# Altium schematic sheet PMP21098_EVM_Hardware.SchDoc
size 431 x 279 mm; Date: Not shown in title block; ApprovedBy: Not shown in title block; CheckedBy: Not shown in title block; Author: Not shown in title block; CompanyName: Not shown in title block; Engineer: Not shown in title block; Organization: Not shown in title block; Address1: Not shown in title block; Address2: Not shown in title block; Address3: Not shown in title block; Address4: Not shown in title block; DocumentNumber: 3; Revision: Use project parameter SCH_Rev; SheetNumber: 3; SheetTotal: 3; PageSetup: Record=PageOptions¦CenterHorizontal=True¦CenterVertical=True¦PrintScale=1.00¦XCorrection=1.00¦YCorrection=1.00¦PrintKind=0¦BorderSize=5000000¦LeftOffset=0¦BottomOffset=0¦Orientation=2¦PaperLength=1000¦PaperWidth=1000¦Scale=100¦PaperSource=15¦PrintQuality=600¦MediaType=1¦DitherType=10¦PaperKind=Letter¦PrintScaleMode=1
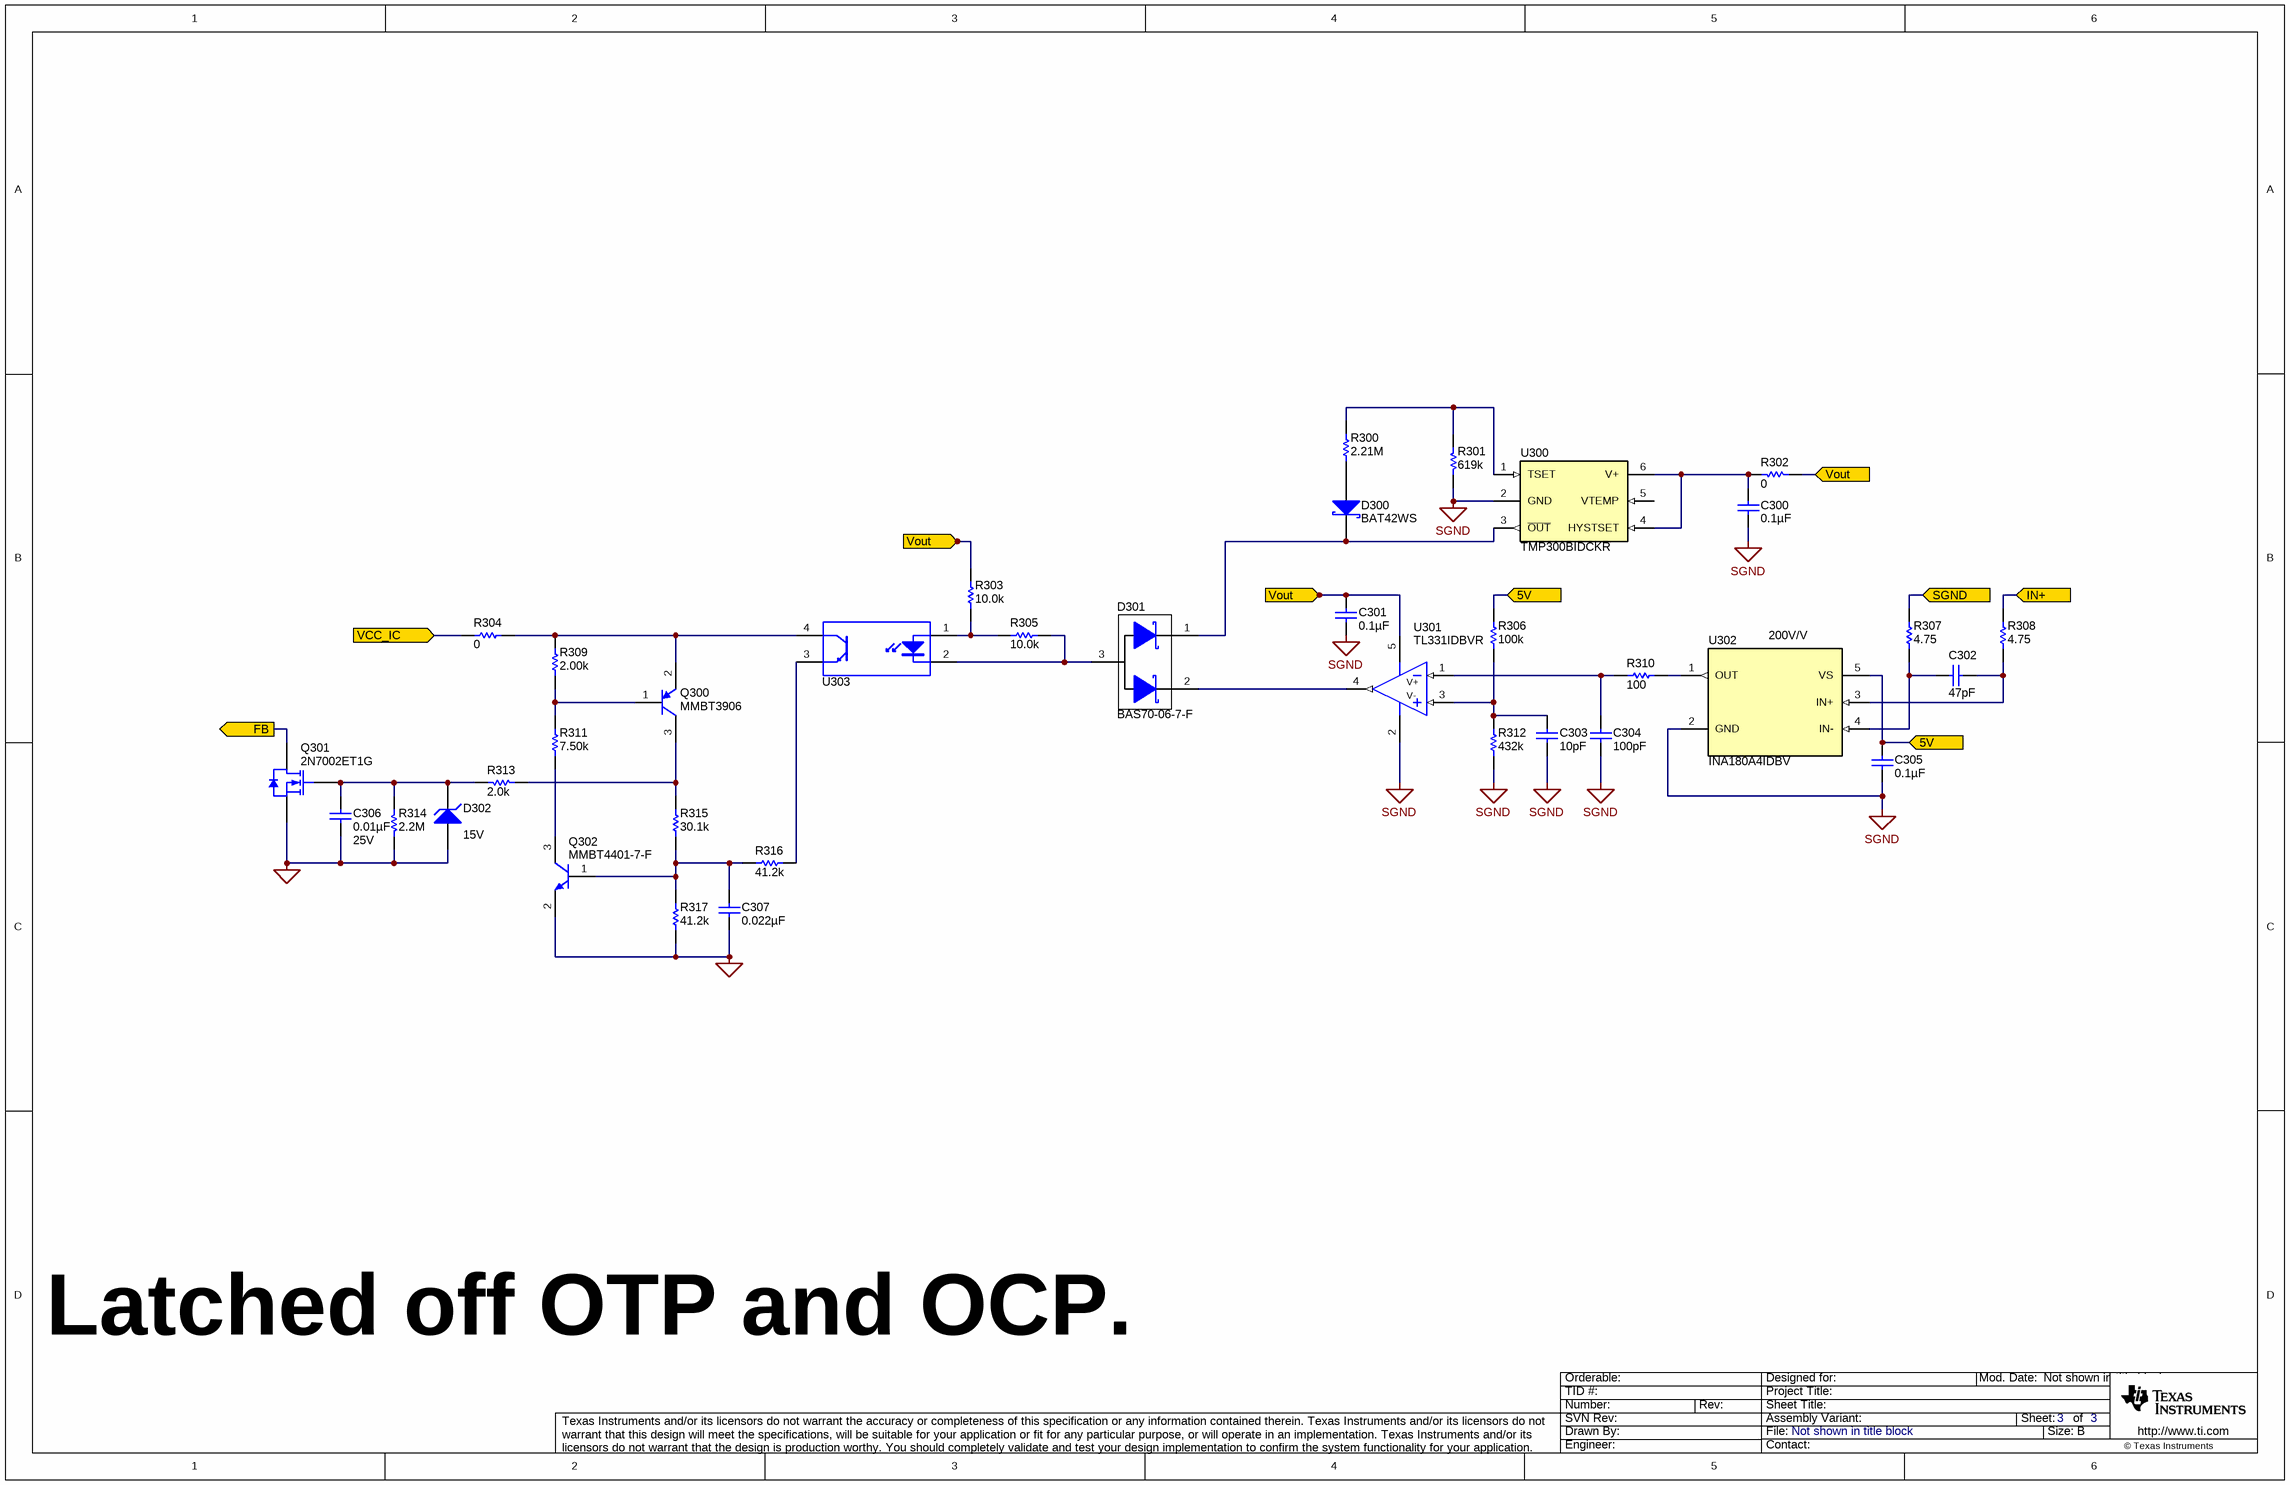
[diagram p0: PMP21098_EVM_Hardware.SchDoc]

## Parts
C300  ValueDisplayed: 0.1µF  [0402]  (hidden comment: GRM155R61C104KA88D)
C301  ValueDisplayed: 0.1µF  [0402]  (hidden comment: GRM155R61C104KA88D)
C302  ValueDisplayed: 47pF  [1206]  (hidden comment: 12067A470JAT2A)
C303  ValueDisplayed: 10pF  [0402]  (hidden comment: GRM1555C1H100RA01D)
C304  ValueDisplayed: 100pF  [0402]  (hidden comment: GRM1555C1H101JA01D)
C305  ValueDisplayed: 0.1µF  [0402]  (hidden comment: GRM155R61E104KA87D)
C306  ValueDisplayed: 0.01µF  Value2: 25V  [0603]  (hidden comment: C0603C103J3GECAUTO)
C307  ValueDisplayed: 0.022µF  [0603]  (hidden comment: C0603C223K5RACTU)
D300  BAT42WS  [sod-323]
D301  BAS70-06-7-F  [SOT-23]
D302  value 15V  [SOD-523]  (hidden comment: MM5Z15VT1G)
Q300  MMBT3906  [SOT-23]
Q301  2N7002ET1G  [SOT-23]
Q302  MMBT4401-7-F  [SOT-23]
R300  ValueDisplayed: 2.21M  [0603]  (hidden comment: CRCW06032M21FKEA)
R301  value 619k  [0402]  (hidden comment: CRCW0402619KFKED)
R302  value 0  [0402]  (hidden comment: ERJ-2GE0R00X)
R303  ValueDisplayed: 10.0k  [0603]  (hidden comment: CRCW060310K0FKEA)
R304  ValueDisplayed: 0  [0603]  (hidden comment: CRCW06030000Z0EA)
R305  ValueDisplayed: 10.0k  [0603]  (hidden comment: CRCW060310K0FKEA)
R306  ValueDisplayed: 100k  [0402]  (hidden comment: CRCW0402100KFKED)
R307  ValueDisplayed: 4.75  [0402]  (hidden comment: CRCW04024R75FKED)
R308  ValueDisplayed: 4.75  [0402]  (hidden comment: CRCW04024R75FKED)
R309  ValueDisplayed: 2.00k  [CPF0603]  (hidden comment: CPF0603B2K0E)
R310  ValueDisplayed: 100  [0402]  (hidden comment: ATC504L1000FTNCFT)
R311  ValueDisplayed: 7.50k  [0603]  (hidden comment: RC0603FR-077K5L)
R312  ValueDisplayed: 432k  [0603]  (hidden comment: CRCW0603432KFKEA)
R313  ValueDisplayed: 2.0k  [0603]  (hidden comment: RC0603JR-072KL)
R314  ValueDisplayed: 2.2M  [0603]  (hidden comment: CRCW06032M20JNEA)
R315  ValueDisplayed: 30.1k  [0603]  (hidden comment: CRCW060330K1FKEA)
R316  ValueDisplayed: 41.2k  [0603]  (hidden comment: CRCW060341K2FKEA)
R317  ValueDisplayed: 41.2k  [0603]  (hidden comment: CRCW060341K2FKEA)
U300  TMP300BIDCKR  [DCK0006A_N]
U301  TL331IDBVR  [DBV0005A_N]
U302  INA180A4IDBV  [DBV0005A_N]
U303  FOD817D  [DIP-4]  (value not drawn)

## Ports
5V (in), FB (out), IN+ (in), SGND (in), VCC_IC (in), Vout (in)

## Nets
GND: C306.2 C307.2 D302.2(A) Q301.2(S) Q302.2(E) R314.1 R317.1
SGND: C300.2 C301.2 C303.2 C304.2 C305.2 R301.1 R312.1 U300.2(GND) U301.2(V-/GND) U302.2(GND)
5V: C305.1 R306.2 U302.5(VS) ; port 5V
FB: Q301.3(D) ; port FB
IN+: R308.2 ; port IN+
SGND: R307.2 ; port SGND  [a separate net that carries the same name]
VCC_IC: R304.1 ; port VCC_IC
Vout: C301.1 R302.1 R303.2 U301.5(V+) ; port Vout
NetC300_1: C300.1 R302.2 U300.4(HYSTSET) U300.6(V+)
NetC302_1: C302.1 R308.1 U302.3(IN+)
NetC302_2: C302.2 R307.1 U302.4(IN-)
NetC303_1: C303.1 R306.1 R312.2 U301.3(IN+)
NetC304_1: C304.1 R310.2 U301.1(IN-)
NetC306_1: C306.1 D302.1(K) Q301.1(G) R313.2 R314.2
NetC307_1: C307.1 Q302.1(B) R315.1 R316.1 R317.2
NetD300_1: D300.1(K) D301.1(A) U300.3(~{OUT})
NetD300_2: D300.2(A) R300.1
NetD301_2: D301.2(K) U301.4(OUT)
NetD301_3: D301.3(A) R305.1 U303.2(K)
NetQ300_1: Q300.1(B) R309.1 R311.2
NetQ300_2: Q300.2(E) R304.2 R309.2 U303.4(C)
NetQ300_3: Q300.3(C) R313.1 R315.2
NetQ302_3: Q302.3(C) R311.1
NetR300_2: R300.2 R301.2 U300.1(TSET)
NetR303_1: R303.1 R305.2 U303.1(A)
NetR310_1: R310.1 U302.1(OUT)
NetR316_2: R316.2 U303.3(E)

Not connected (* = marked no-connect by the designer): U300 5(VTEMP)

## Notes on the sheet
- (near U302) 200V/V
- Latched off OTP and OCP.

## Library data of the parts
C300 C301 = GRM155R61C104KA88D: CAP, CERM, 0.1uF, 16V, +/-10%, X5R, 0402; Manufacturer: MuRata; Polarized: N; CompType: Capacitor; U/M: EA; Cap_F: 0.0000001; Tolerance_%: 10; Value1: Unknown; VDC_V: 16; TaMin_C: -55; TaMax_C: 85
C302 = 12067A470JAT2A: CAP, CERM, 47 pF, 500 V,+/- 5%, C0G/NP0, 1206; Manufacturer: AVX; Polarized: N; CompType: Capacitor; Value: 47pF; U/M: EA; Cap_F: 0.000000000047; Tolerance_%: 5; VDC_V: 500; Value2: 500V; TaMin_C: -55; TaMax_C: 125; SizeArea_mm2: 5.12; SizeAreaWB_mm2: 10.92; SizeX_mm: 3.2; SizeY_mm: 1.6; SizeZ_mm: 1.35; AEC Category: Q200; Green_Lifecycle: Not Set; Green_REACh: Incomplete
C303 = GRM1555C1H100RA01D: CAP, CERM, 10 pF, 50 V,+/- 4%, C0G/NP0, 0402; Manufacturer: MuRata; Polarized: N; CompType: Capacitor; Value: 10pF; U/M: EA; Cap_F: 0.00000000001; Tolerance_%: 4; VDC_V: 50; Value2: 50V; TaMin_C: -55; TaMax_C: 125; SizeArea_mm2: 0.5; SizeAreaWB_mm2: 3; SizeX_mm: 1; SizeZ_mm: 0.6; AEC Category: Q200
C304 = GRM1555C1H101JA01D: CAP, CERM, 100 pF, 50 V,+/- 5%, C0G/NP0, 0402; Manufacturer: MuRata; Polarized: N; CompType: Capacitor; Value: 100pF; U/M: EA; Cap_F: 0.0000000001; Tolerance_%: 5; VDC_V: 50; Value2: 50V; TaMin_C: -55; TaMax_C: 125; SizeArea_mm2: 0.5; SizeAreaWB_mm2: 3; SizeX_mm: 1; SizeZ_mm: 0.6; AEC Category: Q200; Green_Lifecycle: Active; Green_REACh: Passed
C305 = GRM155R61E104KA87D: CAP, CERM, 0.1 µF, 25 V, +/- 10%, X5R, 0402; Manufacturer: MuRata; Polarized: N; CompType: Capacitor; Value: 0.1uF; U/M: EA; Cap_F: 0.0000001; Tolerance_%: 10; Value1: Unknown; VDC_V: 25; Value2: 25V; TaMin_C: -55; TaMax_C: 85
C306 = C0603C103J3GECAUTO: CAP, CERM, 0.01 µF, 25 V,+/- 5%, C0G/NP0, AEC-Q200 Grade 1, 0603; Manufacturer: Kemet; Polarized: N; CompType: Capacitor; Value: 0.01uF; U/M: EA; Cap_F: 0.00000001; Tolerance_%: 5; VDC_V: 25; TaMin_C: -55; TaMax_C: 125; SizeArea_mm2: 1.28; SizeAreaWB_mm2: 4.68; SizeX_mm: 1.6; SizeY_mm: 0.8; SizeZ_mm: 1; AEC Category: Q200; AEC Qualified: Y
C307 = C0603C223K5RACTU: CAP, CERM, 0.022 µF, 50 V,+/- 10%, X7R, 0603; Manufacturer: Kemet; Polarized: N; CompType: Capacitor; Value: 0.022uF; U/M: EA; Cap_F: 0.000000022; Tolerance_%: 10; VDC_V: 50; Value2: 50V; TaMin_C: -55; TaMax_C: 125; SizeArea_mm2: 1.28; SizeAreaWB_mm2: 4.68; SizeX_mm: 1.6; SizeY_mm: 0.8; SizeZ_mm: 1; AEC Category: Q200; Green_Lifecycle: Active; Green_REACh: Passed
D300 = BAT42WS-7-F: Diode, Schottky, 30V, 0.2A, SOD-323; Manufacturer: Diodes Inc.; Value: 1V; U/M: EA; Vf_V: 1; Io_A: 0.2; Vr_V: 30
D301 = BAS70-06-7-F: Diode, Schottky, 70 V, 0.07 A, SOT-23; Manufacturer: Diodes Inc.; SymbolCreator: a0412235; U/M: EA; Vf_V: 1.7; Value: 70V; Value1: 0.07A; Value2: 1.7V; Io_A: 0.07; Vr_V: 70; SizeAreaWB_mm2: 14; SizeArea_mm2: 7.5; SizeX_mm: 2.5; SizeY_mm: 3; SizeZ_mm: 1.1; AEC Category: Q101; Green_Lifecycle: Not Set; Green_REACh: Incomplete
D302 = MM5Z5V6ST1G: DIODE ZENER 15V 200MW SOD523; Manufacturer: ON Semiconductor; SymbolCreator: a0412235; U/M: EA; Power_W: 0.5; Vz_V: 15; Value1: 0.5W; RJA_CperW: 250; SizeAreaWB_mm2: 5.13; SizeArea_mm2: 1.53; SizeX_mm: 1.7; SizeY_mm: 0.9; SizeZ_mm: 0.65; AEC Category: Q101
Q300 = MMBT3906, Fairchild Semiconductor: Transistor, PNP, 40 V, 0.2 A, SOT-23; CompType: BJT; PNP: 1; NPN: 0; Vceo_V: 40; Vcesat1_V: 0.25; Value: 40 V; IcRated_A: 0.2; Value1: 0.2 A; HfeMax: 300; TaMin_C: -55; TaMax_C: 150; SizeAreaWB_mm2: 14; SizeArea_mm2: 7.5; SizeX_mm: 2.5; SizeY_mm: 3; SizeZ_mm: 1.1; U/M: EA; AEC Category: Q101; Green_Lifecycle: Active; Green_REACh: Passed
Q301 = 2N7002ET1G: MOSFET, N-CH, 60V, 0.26A, SOT-23; Manufacturer: ON Semiconductor; Alternate Manufacturer: None; U/M: EA; ChType: N; VdsMax_V: 60; Value1: 3 ohm; Rdson45_Ohm: 3; Value2: 0.81 nC; QgTyp_nC: 0.81; Vgs_V: 20; IdsMax_A: 0.26
Q302 = MMBT4401-7-F, Diodes Inc.: Transistor, NPN, 40 V, 0.15 A, SOT-23; CompType: BJT; PNP: 0; NPN: 1; Vceo_V: 40; Vcesat1_V: 0.4; Value: 40 V; IcRated_A: 0.15; Value1: 0.15 A; HfeMax: 300; TaMin_C: -55; TaMax_C: 150; SizeAreaWB_mm2: 14; SizeArea_mm2: 7.5; SizeX_mm: 2.5; SizeY_mm: 3; SizeZ_mm: 1.1; U/M: EA; AEC Category: Q101; Green_Lifecycle: Active; Green_REACh: Passed
R300 = CRCW06032M21FKEA: RES, 2.21 M, 1%, 0.1 W, 0603; Manufacturer: Vishay-Dale; CompType: Resistor; Value: 2.21Meg; Res_ohm: 2210000; Value_Code: 2M21; Tolerance_%: 1; Power_W: 0.1; Value2: 0.1W; VDC_V: 75; TempCo: 100 ppm/C; SizeArea_mm2: 1.28; SizeX_mm: 1.6; SizeY_mm: 0.8; EIA_Code: E96; U/M: EA; AEC Category: Q200
R301 = CRCW0402619KFKED: RES, 619k ohm, 1%, 0.063W, 0402; Manufacturer: Vishay-Dale; CompType: Resistor; Res_ohm: 619000; Tolerance_%: 1; Power_W: 0.063; VDC_V: 50; TempCo: 100 ppm/C; EIA_Code: E96; U/M: EA
R302 = ERJ-2GE0R00X: RES, 0 ohm, 5%, 0.063W, 0402; Manufacturer: Panasonic; CompType: Resistor; Value_Code: 0000; Tolerance_%: 5; Power_W: 0.063; VDC_V: 50; TempCo: 600 ppm/C; EIA_Code: E24; U/M: EA
R303 R305 = CRCW060310K0FKEA: RES, 10.0 k, 1%, 0.1 W, 0603; Manufacturer: Vishay-Dale; CompType: Resistor; Value: 10.0k; Res_ohm: 10000; Value_Code: 10k0; Tolerance_%: 1; Power_W: 0.1; Value2: 0.1W; VDC_V: 75; TempCo: 100 ppm/C; SizeArea_mm2: 1.28; SizeX_mm: 1.6; SizeY_mm: 0.8; EIA_Code: E96; U/M: EA; AEC Category: Q200; Green_Lifecycle: Active; Green_REACh: Passed
R304 = CRCW06030000Z0EA: RES, 0, 5%, 0.1 W, 0603; Manufacturer: Vishay-Dale; CompType: Resistor; Value: 0; Value_Code: 0000; Tolerance_%: 5; Power_W: 0.1; Value2: 0.1W; VDC_V: 75; TempCo: 200 ppm/C; SizeArea_mm2: 1.28; SizeX_mm: 1.6; SizeY_mm: 0.8; SizeZ_mm: 1; EIA_Code: E24; U/M: EA; AEC Category: Q200; Green_Lifecycle: Active; Green_REACh: Passed
R306 = CRCW0402100KFKED: RES, 100 k, 1%, 0.063 W, 0402; Manufacturer: Vishay-Dale; CompType: Resistor; Value: 100k; Res_ohm: 100000; Tolerance_%: 1; Power_W: 0.063; Value2: 0.063W; VDC_V: 50; TempCo: 100 ppm/C; SizeArea_mm2: 0.5; SizeZ_mm: 0.6; EIA_Code: E96; U/M: EA; AEC Category: Q200; Green_Lifecycle: Active; Green_REACh: Passed
R307 R308 = CRCW04024R75FKED: RES, 4.75, 1%, 0.063 W, 0402; Manufacturer: Vishay-Dale; CompType: Resistor; Value: 4.75; Value_Code: 4R75; Tolerance_%: 1; Power_W: 0.063; Value2: 0.063W; VDC_V: 50; TempCo: 100 ppm/C; SizeArea_mm2: 0.5; SizeZ_mm: 0.6; EIA_Code: E96; U/M: EA; AEC Category: Q200
R309 = CPF0603B2K0E: RES, 2.00 k, 0.1%, 0.063 W, 0603; Manufacturer: TE Connectivity; CompType: Resistor; Value: 2.00k; Res_ohm: 2000; Value_Code: 2k00; Tolerance_%: 0.1; Power_W: 0.063; Value2: 0.063W; VDC_V: 50; TempCo: 25 ppm/C; SizeArea_mm2: 1.24; SizeX_mm: 1.55; SizeY_mm: 0.8; SizeZ_mm: 0.55; EIA_Code: E192; U/M: EA; AEC Category: Q200; AEC Qualified: N; Green_Lifecycle: Active; Green_REACh: Passed
R310 = ATC504L1000FTNCFT: RES, 100, 1%, 0.125 W, AEC-Q200 Grade 1, 0402; Manufacturer: AT Ceramics; CompType: Resistor; Value: 100; Value_Code: 100R; Tolerance_%: 1; Power_W: 0.125; Value2: 0.125W; TempCo: ppm/C; SizeArea_mm2: 0.5; SizeZ_mm: 0.6; EIA_Code: E96; U/M: EA; AEC Category: Q200; AEC Qualified: Y
R311 = RC0603FR-077K5L: RES, 7.50 k, 1%, 0.1 W, 0603; Manufacturer: Yageo America; CompType: Resistor; Value: 7.50k; Res_ohm: 7500; Value_Code: 7k50; Tolerance_%: 1; Power_W: 0.1; Value2: 0.1W; VDC_V: 150; TempCo: 200 ppm/C; SizeArea_mm2: 1.28; SizeX_mm: 1.6; SizeY_mm: 0.8; EIA_Code: E96; U/M: EA; AEC Category: Q200; Green_Lifecycle: Active; Green_REACh: Passed
R312 = CRCW0603432KFKEA: RES, 432 k, 1%, 0.1 W, 0603; Manufacturer: Vishay-Dale; CompType: Resistor; Value: 432k; Res_ohm: 432000; Tolerance_%: 1; Power_W: 0.1; Value2: 0.1W; VDC_V: 75; TempCo: 100 ppm/C; SizeArea_mm2: 1.28; SizeX_mm: 1.6; SizeY_mm: 0.8; EIA_Code: E96; U/M: EA; AEC Category: Q200; Green_Lifecycle: Active; Green_REACh: Passed
R313 = RC0603JR-072KL: RES, 2.0 k, 5%, 0.1 W, 0603; Manufacturer: Yageo America; CompType: Resistor; Value: 2.0k; Res_ohm: 2000; Value_Code: 2k00; Tolerance_%: 5; Power_W: 0.1; Value2: 0.1W; VDC_V: 50; TempCo: 100 ppm/C; SizeArea_mm2: 1.28; SizeX_mm: 1.6; SizeY_mm: 0.8; SizeZ_mm: 1; EIA_Code: E24; U/M: EA; AEC Category: Q200; Green_Lifecycle: Active; Green_REACh: Passed
R314 = CRCW06032M20JNEA: RES, 2.2 M, 5%, 0.1 W, 0603; Manufacturer: Vishay-Dale; CompType: Resistor; Value: 2.2Meg; Res_ohm: 2200000; Value_Code: 2M20; Tolerance_%: 5; Power_W: 0.1; Value2: 0.1W; VDC_V: 75; TempCo: 200 ppm/C; SizeArea_mm2: 1.28; SizeX_mm: 1.6; SizeY_mm: 0.8; SizeZ_mm: 1; EIA_Code: E24; U/M: EA; AEC Category: Q200
R315 = CRCW060330K1FKEA: RES, 30.1 k, 1%, 0.1 W, 0603; Manufacturer: Vishay-Dale; CompType: Resistor; Value: 30.1k; Res_ohm: 30100; Value_Code: 30k1; Tolerance_%: 1; Power_W: 0.1; Value2: 0.1W; VDC_V: 75; TempCo: 100 ppm/C; SizeArea_mm2: 1.28; SizeX_mm: 1.6; SizeY_mm: 0.8; EIA_Code: E96; U/M: EA; AEC Category: Q200; Green_Lifecycle: Active; Green_REACh: Passed
R316 R317 = CRCW060341K2FKEA: RES, 41.2 k, 1%, 0.1 W, 0603; Manufacturer: Vishay-Dale; CompType: Resistor; Value: 41.2k; Res_ohm: 41200; Value_Code: 41k2; Tolerance_%: 1; Power_W: 0.1; Value2: 0.1W; VDC_V: 75; TempCo: 100 ppm/C; SizeArea_mm2: 1.28; SizeX_mm: 1.6; SizeY_mm: 0.8; EIA_Code: E96; U/M: EA; AEC Category: Q200
U300 = TMP300BIDCKR: Resistor-Programmable, up to 18V-Capable Temp Switch and Analog Out Sensor, DCK0006A (SOT-SC70-6); Alternate PartNumber: TMP300BIDCKT; Manufacturer: Texas Instruments; SymbolCreator: a0412235; SizeArea_mm2: 4.2; SizeAreaWB_mm2: 9.3; SizeX_mm: 2.1; SizeY_mm: 2; SizeZ_mm: 1.1; CompType: IC; U/M: EA; Green_Lifecycle: Active; Green_REACh: Passed
U301 = TL331IDBVR: SINGLE DIFFERENTIAL COMPARATOR, DBV0005A (SOT-23-5); Alternate PartNumber: TL331IDBVT; Manufacturer: Texas Instruments; SymbolCreator: a0411947; SizeArea_mm2: 8.12; SizeAreaWB_mm2: 14.82; SizeX_mm: 2.8; SizeY_mm: 2.9; SizeZ_mm: 1.45; CompType: IC; U/M: EA; Green_Lifecycle: Active; Green_REACh: Passed
U302 = INA180A4IDBV: Low- and High-Side Measurement, Multichannel, Voltage Output, Current-Sense Amplifier, DBV0005A (SOT-23-5); Manufacturer: Texas Instruments; SymbolCreator: a0411947; SizeArea_mm2: 8.12; SizeAreaWB_mm2: 14.82; SizeX_mm: 2.8; SizeY_mm: 2.9; SizeZ_mm: 1.45; CompType: IC; U/M: EA
U303 = FOD817A: OPTOISOLATOR 5KV TRANSISTOR 4DIP; Manufacturer: Fairchild Semiconductor; CTR (Min): 300%; CTR (Max): 600%; Voltage_Isolation_Vrms: 5000V; CompType: Optocoupler; SizeAreaWB_mm2: 71.064; SizeArea_mm2: 40.304; SizeX_mm: 8.8; SizeY_mm: 4.58; SizeZ_mm: 5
